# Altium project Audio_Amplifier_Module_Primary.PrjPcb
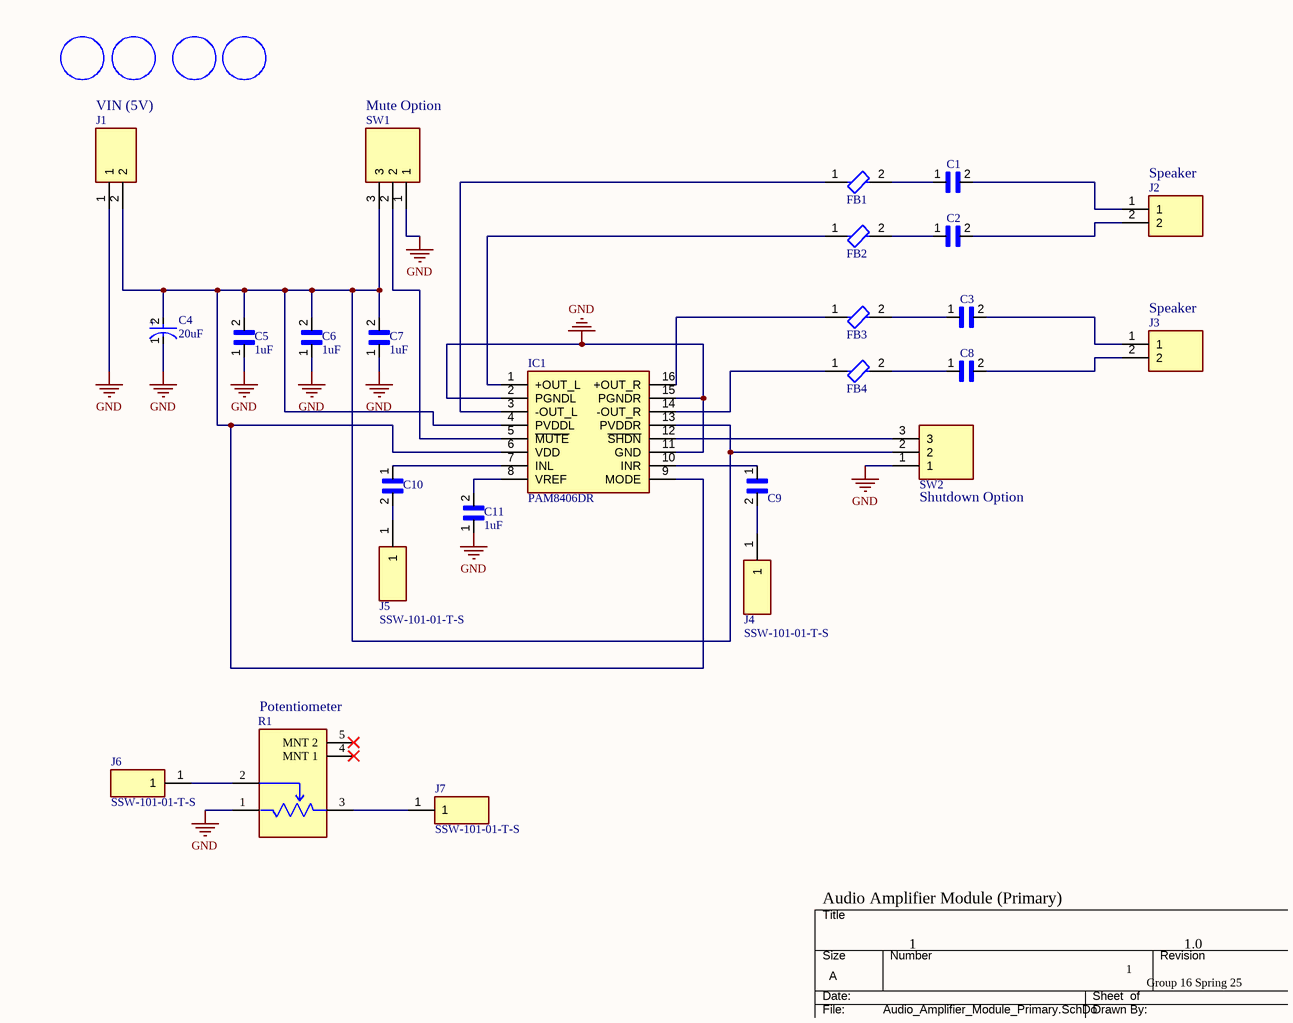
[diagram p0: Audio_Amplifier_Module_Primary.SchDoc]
1 sheet, 30 parts. Net scope: global (net labels, ports and power ports of the same name join across sheets).
Board file: Audio_Amplifier_Module_Primary.PcbDoc

## Sheet Audio_Amplifier_Module_Primary.SchDoc
size A; SheetNumber: 1; SheetTotal: 1

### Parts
*  Mounting Hole  [MTHNP3P2MM]  (value not drawn)
*1  Mounting Hole  [MTHNP3P2MM]  (value not drawn)
*2  Mounting Hole  [MTHNP3P2MM]  (value not drawn)
*3  Mounting Hole  [MTHNP3P2MM]  (value not drawn)
C1  FA16X7R1E106KRU00  [CAPRB250W50L550T350H600]  (value not drawn)
C2  FA16X7R1E106KRU00  [CAPRB250W50L550T350H600]  (value not drawn)
C3  FA16X7R1E106KRU00  [CAPRB250W50L550T350H600]  (value not drawn)
C4  20uF  [FP-EEU-FR1H101B-MFG]
C5  1uF  [CAPRB250W50L550T350H600]
C6  1uF  [CAPRB250W50L550T350H600]
C7  1uF  [CAPRB250W50L550T350H600]
C8  FA16X7R1E106KRU00  [CAPRB250W50L550T350H600]  (value not drawn)
C9  FA16X7R1E106KRU00  [CAPRB250W50L550T350H600]  (value not drawn)
C10  FA16X7R1E106KRU00  [CAPRB250W50L550T350H600]  (value not drawn)
C11  1uF  [CAPRB250W50L550T350H600]
FB1  MPZ1608S221ATA00  [FP-MPZ1608-0_8-MFG]  (value not drawn)
FB2  MPZ1608S221ATA00  [FP-MPZ1608-0_8-MFG]  (value not drawn)
FB3  MPZ1608S221ATA00  [FP-MPZ1608-0_8-MFG]  (value not drawn)
FB4  MPZ1608S221ATA00  [FP-MPZ1608-0_8-MFG]  (value not drawn)
IC1  PAM8406DR  [SOIC127P600X126-16N]
J1  VIN (5V)  [2828372]
J2  Speaker  [2828372]
J3  Speaker  [2828372]
J4  SSW-101-01-T-S  [SSW-101-XX-YYY-S]
J5  SSW-101-01-T-S  [SSW-101-XX-YYY-S]
J6  SSW-101-01-T-S  [SSW-101-XX-YYY-S]
J7  SSW-101-01-T-S  [SSW-101-XX-YYY-S]
R1  Potentiometer  [FP-PTV09A-4-MFG]
SW1  Mute Option  [RHDR3W80P0X254_1X3_812X254X850P]
SW2  Shutdown Option  [RHDR3W80P0X254_1X3_812X254X850P]

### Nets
GND: C4.1(C) C5.1 C6.1 C7.1 C11.1 IC1.2(PGNDL) IC1.11(GND) IC1.15(PGNDR) J1.1 R1.1 SW1.1 SW2.1
NetC1_1: C1.1 FB1.2
NetC1_2: C1.2 J2.1
NetC2_1: C2.1 FB2.2
NetC2_2: C2.2 J2.2
NetC3_1: C3.1 FB3.2
NetC3_2: C3.2 J3.1
NetC4_2: C4.2(A) C5.2 C6.2 C7.2 IC1.4(PVDDL) IC1.6(VDD) IC1.9(MODE) IC1.13(PVDDR) J1.2 SW1.3 SW2.2
NetC8_1: C8.1 FB4.2
NetC8_2: C8.2 J3.2
NetC9_1: C9.1 IC1.10(INR)
NetC9_2: C9.2 J4.1
NetC10_1: C10.1 IC1.7(INL)
NetC10_2: C10.2 J5.1
NetC11_2: C11.2 IC1.8(VREF)
NetFB1_1: FB1.1 IC1.3(-OUT_L)
NetFB2_1: FB2.1 IC1.1(+OUT_L)
NetFB3_1: FB3.1 IC1.16(+OUT_R)
NetFB4_1: FB4.1 IC1.14(-OUT_R)
NetIC1_5: IC1.5(~{MUTE}) SW1.2
NetIC1_12: IC1.12(~{SHDN}) SW2.3
NetJ6_1: J6.1 R1.2
NetJ7_1: J7.1 R1.3

Not connected (* = marked no-connect by the designer): R1 4(MNT_1)* 5(MNT_2)*

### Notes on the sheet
- Audio Amplifier Module (Primary)
- 1
- 1.0
- Group 16 Spring 25

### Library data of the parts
C1-C3 C8-C10 = CMP-030-000002-1: 10 ÂµF Â±10% 25V Ceramic Capacitor X7R Radial; MF: TDK
C4 = CMP-05427-000020-1: CAP ALUM 100UF 20% 50V RADIAL; Life (Hours): 6000Hour; Ripple Current: 870mA; Lead Diameter: 0.6mm; Impedance: 61mR
C5-C7 C11 = CMP-030-000003-1: 1 ÂµF Â±10% 25V Ceramic Capacitor X7R Radial; MP: FA16X7R1E105KNU06; MF: TDK
FB1-FB4 = CMP-08257-000028-1: Power line Ferrite Bead 220Ω @ 100MHz 2.2A DCR 0.05Ω SMD 0603; DC Resistance (DCR): 50mR; Tolerance: 25%; Impedance: 220R
IC1 = CMP-005-000000-1: DiodesZetex PAM8406DR 2-Channel Audio Amplifier; Manufacturer_Name: Diodes Incorporated
J1-J3 = 282837-2: Connector 282837-2; Manufacturer_Name: TE Connectivity
J4-J7 = SSW-101-01-T-S: Connector; Manufacturer_Name: SAMTEC
R1 = CMP-00002-1: Rotary Potentiometer, Carbon Element, 10 kOhm, 1Turn, Linear, 50 mW, ± 20% PTV09A-4225F-B103; Actuator Diameter: 0.236inch; Actuator Length: 0.984inch; Hole Diameter: 9.1mm; Max Power Dissipation: 50mW; Number of Gangs: 1; Value: 10kR
SW1 SW2 = PPTC031LFBN-RC: Connector PPTC031LFBN-RC; Manufacturer_Name: Sullins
